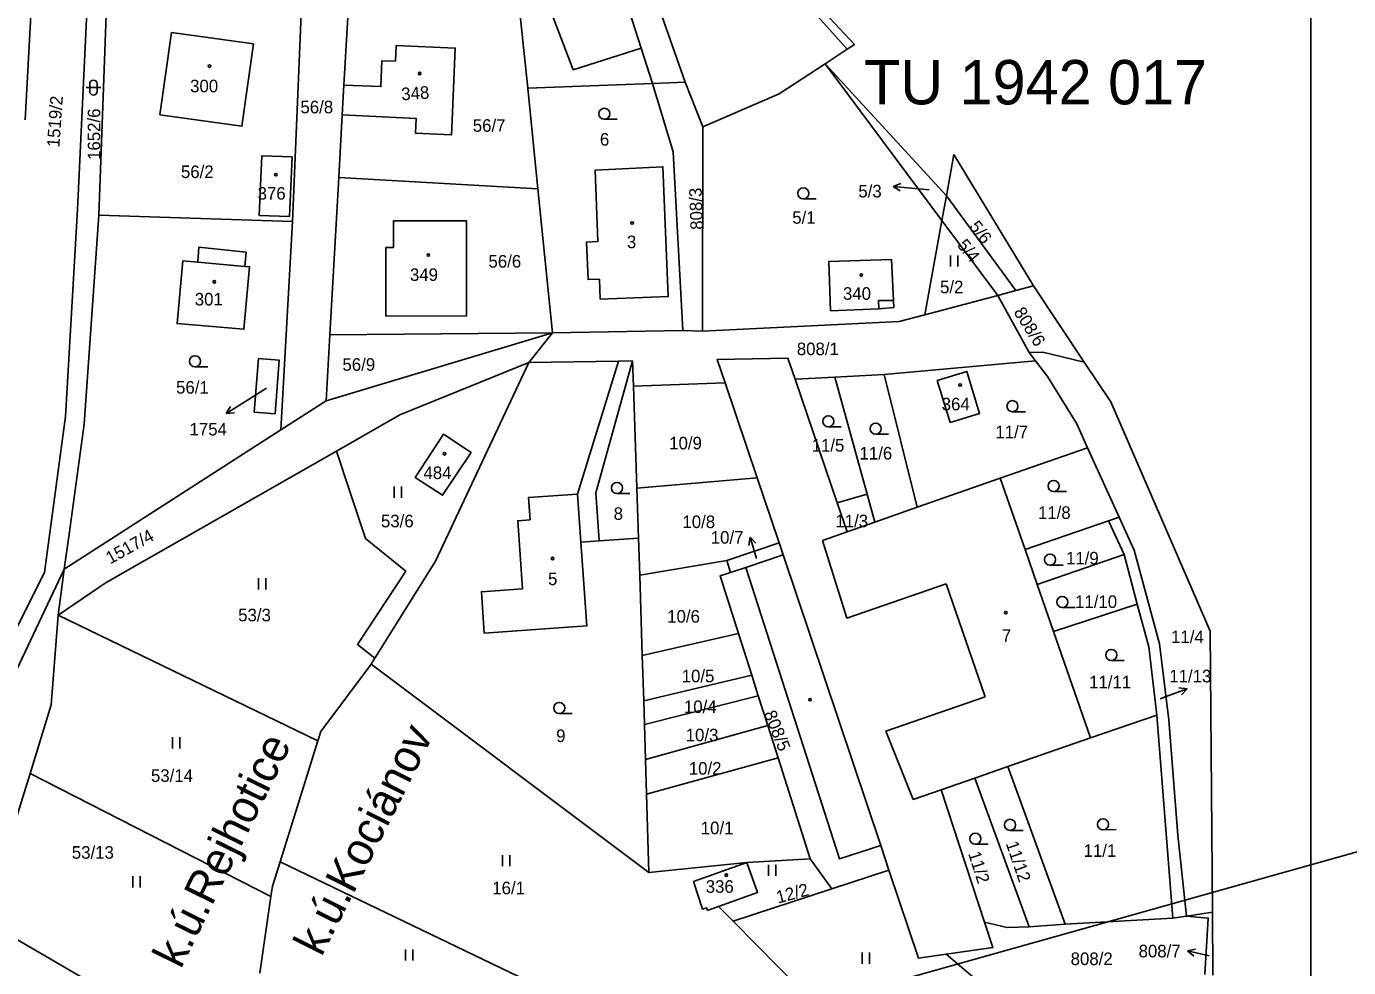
# Model space of a CAD drawing. Extents: x -553916 to -552953, y -1067469 to -1066637.
# Drawn here: x -553473.7 to -553294.9, y -1066945.3 to -1066818.1 of the extents above; entities that cross this region are included whole.
import ezdxf

# ---------------------------------------------------------------- set-up
doc = ezdxf.new("R2010")
doc.units = 0
for name, color, linetype in [('Hranice parcel', 7, 'Continuous'), ('Parcelní čísla', 7, 'Continuous'), ('Pop  PČ popisy', 7, 'Continuous'), ('Vnitřní kresba', 7, 'Continuous'), ('Vrstva 1', 7, 'Continuous'), ('Vrstva 2', 7, 'Continuous'), ('Vrstva 28', 7, 'Continuous'), ('Značky budov', 7, 'Continuous'), ('Značky kultur', 7, 'Continuous')]:
    doc.layers.add(name, color=color, linetype=linetype)

msp = doc.modelspace()

# ---------------------------------------------------------------- linework, layer by layer
at = {"layer": 'Hranice parcel'}
for p, q in [((-553395.45, -1066784.17), (-553361.7, -1066820.54)), ((-553473.84, -1066830.72), (-553472.63, -1066808.29)), ((-553462.79, -1066813.1), (-553463.9, -1066843.58)), ((-553362.67, -1066821.17), (-553369.61, -1066813.45)), ((-553437.72, -1066844.45), (-553436.47, -1066815.36)), ((-553430.14, -1066815.28), (-553430.74, -1066826)), ((-553406.9, -1066816.6), (-553405.9, -1066826.43)), ((-553406.9, -1066816.6), (-553405.9, -1066826.43)), ((-553454.09, -1066818.88), (-553455.64, -1066830.01)), ((-553365.67, -1066823.14), (-553362.67, -1066821.17)), ((-553362.67, -1066821.17), (-553361.7, -1066820.54)), ((-553349.88, -1066844.3), (-553365.67, -1066823.14)), ((-553349.28, -1066841), (-553365.67, -1066823.14)), ((-553430.97, -1066830.01), (-553430.74, -1066826)), ((-553405.9, -1066826.43), (-553389.03, -1066825.78)), ((-553405.9, -1066826.43), (-553404.51, -1066840.02)), ((-553405.9, -1066826.43), (-553404.51, -1066840.02)), ((-553389.03, -1066825.78), (-553384.58, -1066825.61)), ((-553384.58, -1066825.61), (-553382.23, -1066831.65)), ((-553430.97, -1066830.01), (-553431.45, -1066838.5)), ((-553382.23, -1066831.65), (-553382.27, -1066859.27)), ((-553349.28, -1066841), (-553348.26, -1066835.41)), ((-553348.26, -1066835.41), (-553337.5, -1066853.17)), ((-553431.45, -1066838.5), (-553432.65, -1066859.78)), ((-553404.51, -1066840.02), (-553431.45, -1066838.5)), ((-553404.51, -1066840.02), (-553402.55, -1066859.53)), ((-553404.51, -1066840.02), (-553402.55, -1066859.53)), ((-553349.88, -1066844.3), (-553349.28, -1066841)), ((-553339.87, -1066853.8), (-553349.28, -1066841)), ((-553437.72, -1066844.45), (-553463.9, -1066843.58)), ((-553439.3, -1066872.64), (-553437.72, -1066844.45)), ((-553352.21, -1066857.06), (-553349.88, -1066844.3)), ((-553342.3, -1066854.44), (-553349.88, -1066844.3)), ((-553337.5, -1066853.17), (-553339.87, -1066853.8)), ((-553337.5, -1066853.17), (-553330.62, -1066863.49)), ((-553352.21, -1066857.06), (-553342.3, -1066854.44)), ((-553342.3, -1066854.44), (-553339.87, -1066853.8)), ((-553338.06, -1066862.17), (-553342.3, -1066854.44)), ((-553433.16, -1066868.7), (-553402.55, -1066859.53)), ((-553433.16, -1066868.7), (-553432.65, -1066859.78)), ((-553432.65, -1066859.78), (-553402.55, -1066859.53)), ((-553402.55, -1066859.53), (-553405.75, -1066863.52)), ((-553402.55, -1066859.53), (-553405.75, -1066863.52)), ((-553402.55, -1066859.53), (-553384.93, -1066859.19)), ((-553382.27, -1066859.27), (-553384.93, -1066859.19)), ((-553337.2, -1066863.31), (-553338.06, -1066862.17)), ((-553405.75, -1066863.52), (-553418.35, -1066890.38)), ((-553405.75, -1066863.52), (-553418.35, -1066890.38)), ((-553393.6, -1066863.32), (-553405.75, -1066863.52)), ((-553391.72, -1066863.29), (-553393.6, -1066863.32)), ((-553391.6, -1066866.73), (-553391.72, -1066863.29)), ((-553357.68, -1066865.16), (-553337.2, -1066863.31)), ((-553369.73, -1066865.79), (-553364.36, -1066865.52)), ((-553364.04, -1066882.5), (-553369.73, -1066865.79)), ((-553364.36, -1066865.52), (-553357.68, -1066865.16)), ((-553359.98, -1066881.34), (-553364.36, -1066865.52)), ((-553353.23, -1066883.1), (-553357.68, -1066865.16)), ((-553391.6, -1066866.73), (-553379.2, -1066866.25)), ((-553391.12, -1066880.5), (-553391.6, -1066866.73)), ((-553379.2, -1066866.25), (-553374.85, -1066879.11)), ((-553439.3, -1066872.64), (-553433.16, -1066868.7)), ((-553468.58, -1066891.47), (-553439.3, -1066872.64)), ((-553429.98, -1066880.85), (-553431.77, -1066875.51)), ((-553342, -1066879.14), (-553330.18, -1066875.07)), ((-553330.18, -1066875.07), (-553325.91, -1066884.44)), ((-553391.12, -1066880.5), (-553374.85, -1066879.11)), ((-553374.85, -1066879.11), (-553371.87, -1066887.91)), ((-553342, -1066879.14), (-553353.23, -1066883.1)), ((-553338.64, -1066888.8), (-553342, -1066879.14)), ((-553390.89, -1066887.26), (-553391.12, -1066880.5)), ((-553359.98, -1066881.34), (-553364.04, -1066882.5)), ((-553358.93, -1066885.11), (-553359.98, -1066881.34)), ((-553353.23, -1066883.1), (-553358.93, -1066885.11)), ((-553338.64, -1066888.8), (-553327.34, -1066884.93)), ((-553325.91, -1066884.44), (-553327.34, -1066884.93)), ((-553327.34, -1066884.93), (-553325.25, -1066889.5)), ((-553396.21, -1066887.64), (-553390.89, -1066887.26)), ((-553390.74, -1066892.28), (-553390.89, -1066887.26)), ((-553371.87, -1066887.91), (-553378.98, -1066890.3)), ((-553337, -1066893.52), (-553338.64, -1066888.8)), ((-553418.35, -1066890.38), (-553426.55, -1066903.5)), ((-553418.35, -1066890.38), (-553426.55, -1066903.5)), ((-553390.74, -1066892.28), (-553378.98, -1066890.3)), ((-553378.98, -1066890.3), (-553378.45, -1066891.91)), ((-553325.25, -1066889.5), (-553337, -1066893.52)), ((-553325.25, -1066889.5), (-553323.46, -1066896.2)), ((-553469.39, -1066897.71), (-553468.58, -1066891.47)), ((-553390.4, -1066903.13), (-553390.74, -1066892.28)), ((-553376.39, -1066891.22), (-553378.45, -1066891.91)), ((-553334.78, -1066899.88), (-553337, -1066893.52)), ((-553323.46, -1066896.2), (-553334.78, -1066899.88)), ((-553470.32, -1066909.81), (-553469.39, -1066897.71)), ((-553469.39, -1066897.71), (-553434.29, -1066914.68)), ((-553329.78, -1066914.26), (-553334.78, -1066899.88)), ((-553426.55, -1066903.5), (-553428.91, -1066901.64)), ((-553390.4, -1066903.13), (-553377.39, -1066900.17)), ((-553377.39, -1066900.17), (-553375.6, -1066905.79)), ((-553426.55, -1066903.5), (-553427.07, -1066904.33)), ((-553426.55, -1066903.5), (-553427.07, -1066904.33)), ((-553390.21, -1066909.27), (-553390.4, -1066903.13)), ((-553427.07, -1066904.33), (-553433.89, -1066913.41)), ((-553427.07, -1066904.33), (-553433.89, -1066913.41)), ((-553427.07, -1066904.33), (-553389.5, -1066932.5)), ((-553390.21, -1066909.27), (-553375.6, -1066905.79)), ((-553375.6, -1066905.79), (-553374.71, -1066908.6)), ((-553390.12, -1066912.46), (-553374.71, -1066908.6)), ((-553374.71, -1066908.6), (-553373.43, -1066912.61)), ((-553473.2, -1066919.09), (-553470.32, -1066909.81)), ((-553390.12, -1066912.46), (-553390.21, -1066909.27)), ((-553389.97, -1066917.2), (-553390.12, -1066912.46)), ((-553320.82, -1066911.2), (-553329.78, -1066914.26)), ((-553320.82, -1066911.2), (-553318.66, -1066938.68)), ((-553433.89, -1066913.41), (-553434.29, -1066914.68)), ((-553433.89, -1066913.41), (-553434.29, -1066914.68)), ((-553389.97, -1066917.2), (-553373.43, -1066912.61)), ((-553373.43, -1066912.61), (-553372.03, -1066917)), ((-553340.98, -1066918.17), (-553329.78, -1066914.26)), ((-553434.29, -1066914.68), (-553439.39, -1066931.05)), ((-553434.29, -1066914.68), (-553439.39, -1066931.05)), ((-553389.83, -1066921.89), (-553389.97, -1066917.2)), ((-553372.03, -1066917), (-553389.83, -1066921.89)), ((-553372.03, -1066917), (-553367.69, -1066930.63)), ((-553473.2, -1066919.09), (-553440.62, -1066935.71)), ((-553345.44, -1066919.72), (-553340.98, -1066918.17)), ((-553340.98, -1066918.17), (-553333.21, -1066939.46)), ((-553338.1, -1066939.82), (-553345.44, -1066919.72)), ((-553389.5, -1066932.5), (-553389.83, -1066921.89)), ((-553317.96, -1066927.42), (-553316.81, -1066938.4)), ((-553439.39, -1066931.05), (-553388.55, -1066955.44)), ((-553376.25, -1066931.13), (-553389.5, -1066932.5)), ((-553383.48, -1066933.71), (-553376.25, -1066931.13)), ((-553367.69, -1066930.63), (-553376.25, -1066931.13)), ((-553364.75, -1066934.68), (-553367.69, -1066930.63)), ((-553357.05, -1066932.15), (-553364.75, -1066934.68)), ((-553440.62, -1066935.71), (-553442.13, -1066946.08)), ((-553440.62, -1066935.71), (-553442.13, -1066946.08)), ((-553364.75, -1066934.68), (-553378.13, -1066939.08)), ((-553380.09, -1066937.09), (-553381.59, -1066937.63)), ((-553378.13, -1066939.08), (-553380.09, -1066937.09)), ((-553318.66, -1066938.68), (-553333.21, -1066939.46)), ((-553316.81, -1066938.4), (-553318.66, -1066938.68)), ((-553316.81, -1066938.4), (-553313.3, -1066937.87)), ((-553313.3, -1066937.87), (-553313.24, -1066946.37)), ((-553333.21, -1066939.46), (-553338.1, -1066939.82)), ((-553349.32, -1066943.54), (-553345.38, -1066946.85))]:
    msp.add_line(p, q, dxfattribs=at)
for points in [[(-553477.08, -1066903.52), (-553471.25, -1066891.92), (-553468.41, -1066870.82), (-553466.8, -1066842.82), (-553465.31, -1066811.26), (-553449.58, -1066745.18), (-553421.6, -1066636.65)], [(-553384.58, -1066825.61), (-553397.51, -1066788.92), (-553395.83, -1066783.77)], [(-553389.03, -1066825.78), (-553390.55, -1066821.01), (-553396.74, -1066801.73)], [(-553455.64, -1066830.01), (-553444.55, -1066831.57), (-553442.98, -1066820.44), (-553454.09, -1066818.88)], [(-553430.74, -1066826), (-553425.75, -1066826.22), (-553425.61, -1066822.71), (-553423.78, -1066822.79), (-553423.68, -1066820.65), (-553415.69, -1066821.01), (-553416.11, -1066830.8), (-553416.18, -1066832.75), (-553421.08, -1066832.49), (-553420.97, -1066830.55), (-553430.97, -1066830.01)], [(-553365.67, -1066823.14), (-553371.88, -1066827.2), (-553382.23, -1066831.65)], [(-553384.93, -1066859.19), (-553386.23, -1066835.02), (-553389.03, -1066825.78)], [(-553438.09, -1066843.79), (-553437.75, -1066835.69), (-553441.85, -1066835.56), (-553442.19, -1066843.65), (-553438.09, -1066843.79)], [(-553396.1, -1066854.97), (-553396.2, -1066852.24), (-553397.74, -1066852.3), (-553397.93, -1066847.23), (-553396.4, -1066847.17), (-553396.78, -1066837.52), (-553387.6, -1066837.08), (-553386.89, -1066854.6), (-553396.1, -1066854.97)], [(-553463.9, -1066843.58), (-553465.86, -1066871.86), (-553467.89, -1066886.72), (-553468.58, -1066891.47)], [(-553424.03, -1066847.95), (-553424.03, -1066844.35), (-553414.18, -1066844.35), (-553414.18, -1066857.22), (-553425.08, -1066857.25), (-553425.08, -1066847.95), (-553424.03, -1066847.95)], [(-553444.13, -1066850.52), (-553443.53, -1066850.58), (-553444.27, -1066859.03), (-553453.31, -1066858.26), (-553452.54, -1066849.78), (-553450.5, -1066849.96), (-553450.36, -1066847.91), (-553443.98, -1066848.58), (-553444.13, -1066850.52)], [(-553364.93, -1066856.54), (-553365.18, -1066849.87), (-553356.7, -1066849.59), (-553356.43, -1066855.14), (-553356.4, -1066856.08), (-553358.41, -1066856.26), (-553364.93, -1066856.54)], [(-553382.27, -1066859.27), (-553355.65, -1066857.97), (-553352.21, -1066857.06)], [(-553338.06, -1066862.17), (-553336.24, -1066862.12), (-553330.62, -1066863.49)], [(-553442.88, -1066870.22), (-553442.32, -1066863), (-553439.49, -1066863.22), (-553440.05, -1066870.46), (-553442.88, -1066870.22)], [(-553431.77, -1066875.51), (-553423.18, -1066870.61), (-553405.75, -1066863.52)], [(-553393.6, -1066863.32), (-553399.15, -1066881.33), (-553405.78, -1066881.79), (-553405.58, -1066884.79), (-553407.24, -1066884.91), (-553406.6, -1066894.14), (-553412.16, -1066894.53), (-553411.78, -1066900.1), (-553397.91, -1066899.13), (-553398.7, -1066887.81), (-553396.21, -1066887.64)], [(-553396.21, -1066887.64), (-553396.66, -1066881.16), (-553391.72, -1066863.29)], [(-553369.73, -1066865.79), (-553370.7, -1066862.94), (-553380.27, -1066863.1), (-553379.2, -1066866.25)], [(-553337.2, -1066863.31), (-553335.6, -1066865.41), (-553331.65, -1066871.83), (-553330.18, -1066875.07)], [(-553330.62, -1066863.49), (-553327.03, -1066868.86), (-553313.59, -1066899.84), (-553313.3, -1066937.87)], [(-553348.76, -1066871.62), (-553344.78, -1066870.4), (-553346.5, -1066864.73), (-553350.51, -1066865.96), (-553348.76, -1066871.62)], [(-553421.1, -1066879.07), (-553417.29, -1066873.23), (-553413.56, -1066875.67), (-553417.4, -1066881.48), (-553421.1, -1066879.07)], [(-553469.39, -1066897.71), (-553462.91, -1066893.26), (-553431.77, -1066875.51)], [(-553428.91, -1066901.64), (-553422.38, -1066891.72), (-553427.81, -1066887.32), (-553429.98, -1066880.85)], [(-553358.93, -1066885.11), (-553362.7, -1066886.44), (-553364.04, -1066882.5)], [(-553325.91, -1066884.44), (-553323.88, -1066888.91), (-553320.46, -1066901.58), (-553319.18, -1066911.82), (-553317.96, -1066927.42)], [(-553371.87, -1066887.91), (-553371.33, -1066889.52), (-553376.39, -1066891.22)], [(-553468.58, -1066891.47), (-553477.31, -1066909.92), (-553483.75, -1066931.3), (-553489.9, -1066939.2)], [(-553378.45, -1066891.91), (-553379.87, -1066892.39), (-553377.39, -1066900.17)], [(-553376.39, -1066891.22), (-553363.74, -1066930.65), (-553358.16, -1066928.83), (-553357.05, -1066932.15)], [(-553323.46, -1066896.2), (-553321.91, -1066901.97), (-553320.82, -1066911.2)], [(-553479.42, -1066936.25), (-553477.68, -1066933.49), (-553473.2, -1066919.09)], [(-553344.1, -1066939.22), (-553349.98, -1066921.31), (-553345.44, -1066919.72)], [(-553439.39, -1066931.05), (-553440.42, -1066934.34), (-553440.62, -1066935.71)], [(-553439.39, -1066931.05), (-553440.42, -1066934.34), (-553440.62, -1066935.71)], [(-553376.25, -1066931.13), (-553374.83, -1066935.2), (-553380.09, -1066937.09)], [(-553357.05, -1066932.15), (-553353.06, -1066944.07), (-553349.32, -1066943.54)], [(-553381.59, -1066937.63), (-553381.72, -1066937.26), (-553382.24, -1066937.44), (-553383.48, -1066933.71)], [(-553444.09, -1066959.55), (-553475.65, -1066941.14), (-553477.33, -1066939.99), (-553479.42, -1066936.25)], [(-553361.44, -1066954.89), (-553365.68, -1066951.68), (-553378.13, -1066939.08)], [(-553349.32, -1066943.54), (-553342.98, -1066942.63), (-553344.1, -1066939.22)], [(-553338.1, -1066939.82), (-553341.07, -1066939.94), (-553344.1, -1066939.22)], [(-553314.33, -1066946.26), (-553313.87, -1066938.65), (-553316.81, -1066938.4)]]:
    msp.add_lwpolyline(points, dxfattribs=at)
at = {"layer": 'Pop  PČ popisy'}
for p, q in [((-553356.49, -1066839.73), (-553355.45, -1066839.32)), ((-553353.5, -1066839.99), (-553356.49, -1066839.73)), ((-553356.49, -1066839.73), (-553355.54, -1066840.31)), ((-553351.59, -1066840.16), (-553353.5, -1066839.99)), ((-553441.2, -1066867.01), (-553444.13, -1066868.85)), ((-553444.13, -1066868.85), (-553446.68, -1066870.44)), ((-553446.68, -1066870.44), (-553446.09, -1066869.49)), ((-553446.68, -1066870.44), (-553445.56, -1066870.33)), ((-553375.82, -1066887.16), (-553376, -1066888.26)), ((-553374.94, -1066890.03), (-553375.82, -1066887.16)), ((-553375.82, -1066887.16), (-553375.05, -1066887.97)), ((-553320.37, -1066908.98), (-553319.53, -1066908.68)), ((-553319.53, -1066908.68), (-553316.71, -1066907.65)), ((-553316.71, -1066907.65), (-553317.82, -1066907.53)), ((-553316.71, -1066907.65), (-553317.48, -1066908.47)), ((-553316.67, -1066943.09), (-553315.59, -1066942.83)), ((-553313.75, -1066943.77), (-553316.67, -1066943.09)), ((-553316.67, -1066943.09), (-553315.81, -1066943.81))]:
    msp.add_line(p, q, dxfattribs=at)
at = {"layer": 'Vnitřní kresba'}
for p, q in [((-553402.7, -1066816.16), (-553399.76, -1066823.95)), ((-553399.76, -1066823.95), (-553390.55, -1066821.01)), ((-553444.13, -1066850.52), (-553450.5, -1066849.96)), ((-553358.45, -1066855.13), (-553356.43, -1066855.14)), ((-553358.41, -1066856.26), (-553358.45, -1066855.13)), ((-553399.15, -1066881.33), (-553398.7, -1066887.81)), ((-553366.02, -1066887.61), (-553362.7, -1066886.44)), ((-553366.02, -1066887.61), (-553362.75, -1066898.09)), ((-553371.33, -1066889.52), (-553358.16, -1066928.83)), ((-553362.75, -1066898.09), (-553349.29, -1066893.44)), ((-553349.29, -1066893.44), (-553344.05, -1066908.75)), ((-553357.47, -1066913.39), (-553344.05, -1066908.75)), ((-553357.47, -1066913.39), (-553353.78, -1066922.63)), ((-553349.98, -1066921.31), (-553353.78, -1066922.63))]:
    msp.add_line(p, q, dxfattribs=at)
at = {"layer": 'Vrstva 1'}
msp.add_lwpolyline([(-553300, -1066816.27), (-553300, -1067100), (-553800, -1067100), (-553800, -1066816.27)], dxfattribs=at)
at = {"layer": 'Vrstva 28'}
msp.add_line((-553261.02, -1066920.51), (-553505.73, -1066989.17), dxfattribs=at)
at = {"layer": 'Značky budov'}
for centre in [(-553448.93, -1066823.44), (-553420.51, -1066824.45), (-553439.96, -1066838.12), (-553391.76, -1066844.66), (-553419.33, -1066848.99), (-553360.78, -1066851.7), (-553448.27, -1066852.62), (-553347.41, -1066866.56), (-553417.15, -1066875.86), (-553402.53, -1066890.03), (-553341.24, -1066897.35), (-553367.72, -1066909.11), (-553379.03, -1066932.85)]:
    msp.add_circle(centre, 0.175, dxfattribs=at)
at = {"layer": 'Značky kultur'}
for p, q in [((-553465.63, -1066826.35), (-553463.63, -1066826.35)), ((-553465.13, -1066825.85), (-553465.13, -1066826.85)), ((-553464.13, -1066826.85), (-553464.13, -1066825.85)), ((-553395.54, -1066830.64), (-553393.79, -1066830.64)), ((-553368.63, -1066841.41), (-553366.88, -1066841.41)), ((-553348.71, -1066850.56), (-553348.71, -1066849.06)), ((-553347.71, -1066850.56), (-553347.71, -1066849.06)), ((-553450.89, -1066864.1), (-553449.14, -1066864.1)), ((-553340.34, -1066870.18), (-553338.59, -1066870.18)), ((-553365.24, -1066872.22), (-553363.49, -1066872.22)), ((-553358.84, -1066873.22), (-553357.09, -1066873.22)), ((-553423.97, -1066881.81), (-553423.97, -1066880.31)), ((-553422.97, -1066881.81), (-553422.97, -1066880.31)), ((-553393.83, -1066881.24), (-553392.08, -1066881.24)), ((-553334.78, -1066880.97), (-553333.03, -1066880.97)), ((-553335.25, -1066890.93), (-553333.5, -1066890.93)), ((-553442.29, -1066894.2), (-553442.29, -1066892.7)), ((-553441.29, -1066894.2), (-553441.29, -1066892.7)), ((-553333.6, -1066896.66), (-553331.85, -1066896.66)), ((-553326.96, -1066903.81), (-553325.21, -1066903.81)), ((-553401.63, -1066910.99), (-553399.88, -1066910.99)), ((-553453.92, -1066915.7), (-553453.92, -1066914.2)), ((-553452.92, -1066915.7), (-553452.92, -1066914.2)), ((-553340.66, -1066926.79), (-553338.91, -1066926.79)), ((-553328.08, -1066926.72), (-553326.33, -1066926.69)), ((-553409.32, -1066931.64), (-553409.32, -1066930.14)), ((-553408.32, -1066931.64), (-553408.32, -1066930.14)), ((-553345.36, -1066928.67), (-553343.61, -1066928.67)), ((-553373.35, -1066932.94), (-553373.35, -1066931.44)), ((-553372.35, -1066932.94), (-553372.35, -1066931.44)), ((-553459.31, -1066934.5), (-553459.31, -1066933)), ((-553458.31, -1066934.5), (-553458.31, -1066933)), ((-553422.44, -1066944.4), (-553422.44, -1066942.9)), ((-553421.44, -1066944.4), (-553421.44, -1066942.9)), ((-553360.66, -1066944.82), (-553360.66, -1066943.32)), ((-553359.66, -1066944.82), (-553359.66, -1066943.32))]:
    msp.add_line(p, q, dxfattribs=at)
for centre in [(-553395.54, -1066829.89), (-553368.63, -1066840.66), (-553450.89, -1066863.35), (-553340.34, -1066869.43), (-553365.24, -1066871.47), (-553358.84, -1066872.47), (-553393.83, -1066880.49), (-553334.78, -1066880.22), (-553335.25, -1066890.18), (-553333.6, -1066895.91), (-553326.96, -1066903.06), (-553401.63, -1066910.24), (-553340.66, -1066926.04), (-553328.1, -1066925.97), (-553345.36, -1066927.92)]:
    msp.add_circle(centre, 0.75, dxfattribs=at)
for centre, start, end in [((-553464.63, -1066825.85), 0, 180), ((-553464.63, -1066826.85), 180, 359.9879)]:
    msp.add_arc(centre, 0.5, start, end, dxfattribs=at)

# ---------------------------------------------------------------- texts
at = {"layer": 'Parcelní čísla'}
for s, p in [('300', (-553451.55, -1066826.98)), ('56/8', (-553436.63, -1066829.83)), ('56/7', (-553413.32, -1066832.32)), ('6', (-553396.13, -1066834.19)), ('56/2', (-553452.79, -1066838.58)), ('376', (-553442.42, -1066841.5)), ('5/3', (-553361.18, -1066841.2)), ('5/1', (-553370.12, -1066844.76)), ('3', (-553392.48, -1066848.06)), ('56/6', (-553411.2, -1066850.69)), ('349', (-553421.82, -1066852.49)), ('340', (-553363.26, -1066855.04)), ('5/2', (-553350.13, -1066854.16)), ('301', (-553450.92, -1066855.81)), ('808/1', (-553369.5, -1066862.53)), ('56/9', (-553430.95, -1066864.64)), ('56/1', (-553453.45, -1066867.73)), ('364', (-553349.91, -1066869.99)), ('1754', (-553451.63, -1066873.39)), ('11/7', (-553342.65, -1066873.76)), ('10/9', (-553386.76, -1066875.27)), ('11/5', (-553367.5, -1066875.57)), ('11/6', (-553361.02, -1066876.64)), ('484', (-553419.99, -1066879.28)), ('8', (-553394.27, -1066884.8)), ('11/8', (-553336.89, -1066884.67)), ('53/6', (-553425.74, -1066885.81)), ('10/8', (-553384.97, -1066885.91)), ('11/3', (-553364.29, -1066885.8)), ('10/7', (-553381.14, -1066888.02)), ('11/9', (-553333.1, -1066890.83)), ('5', (-553403.15, -1066893.62)), ('11/10', (-553331.87, -1066896.71)), ('53/3', (-553445.05, -1066898.52)), ('10/6', (-553387.03, -1066898.7)), ('11/4', (-553318.89, -1066901.47)), ('10/5', (-553385.07, -1066906.77)), ('11/13', (-553319.13, -1066906.78)), ('11/11', (-553329.97, -1066907.58)), ('10/4', (-553384.77, -1066910.92)), ('9', (-553402.05, -1066914.85)), ('10/3', (-553384.53, -1066914.74)), ('10/2', (-553384.11, -1066919.25)), ('53/14', (-553456.85, -1066920.23)), ('10/1', (-553382.49, -1066927.31)), ('11/1', (-553330.72, -1066930.37)), ('53/13', (-553467.55, -1066930.62)), ('16/1', (-553410.69, -1066935.43)), ('336', (-553381.82, -1066935.23)), ('808/7', (-553323.28, -1066943.96)), ('808/2', (-553332.47, -1066945))]:
    msp.add_text(s, height=1.7, dxfattribs=at).set_placement(p)
for s, rotation, p in [('348', 4, (-553422.93, -1066828.08)), ('1519/2', 85.9988, (-553469.23, -1066834.46)), ('1652/6', 90, (-553463.7, -1066836.13)), ('808/3', 92, (-553382.18, -1066845.55)), ('5/6', 308, (-553346.28, -1066845.17)), ('5/4', 309, (-553347.91, -1066847.69)), ('808/6', 302, (-553340.23, -1066856.7)), ('1517/4', 29, (-553462.36, -1066890.84)), ('7', 1, (-553341.76, -1066901.32)), ('808/5', 292, (-553374, -1066910.97)), ('11/12', 289, (-553341.26, -1066928.57)), ('11/2', 288, (-553346.35, -1066929.92)), ('12/2', 15, (-553372.03, -1066936.69))]:
    msp.add_text(s, height=1.7, rotation=rotation, dxfattribs=at).set_placement(p)
at = {"layer": 'Pop  PČ popisy'}
for s, rotation, p in [('k.ú.Kociánov', 63.1841, (-553433.79, -1066943.99)), ('k.ú.Rejhotice', 63.7917, (-553452.81, -1066945.64))]:
    msp.add_text(s, height=4.4, rotation=rotation, dxfattribs=at).set_placement(p)
at = {"layer": 'Vrstva 2'}
msp.add_text('TU 1942 017', height=6, dxfattribs=at).set_placement((-553360.41, -1066828.62))

doc.saveas('drawing.dxf')
